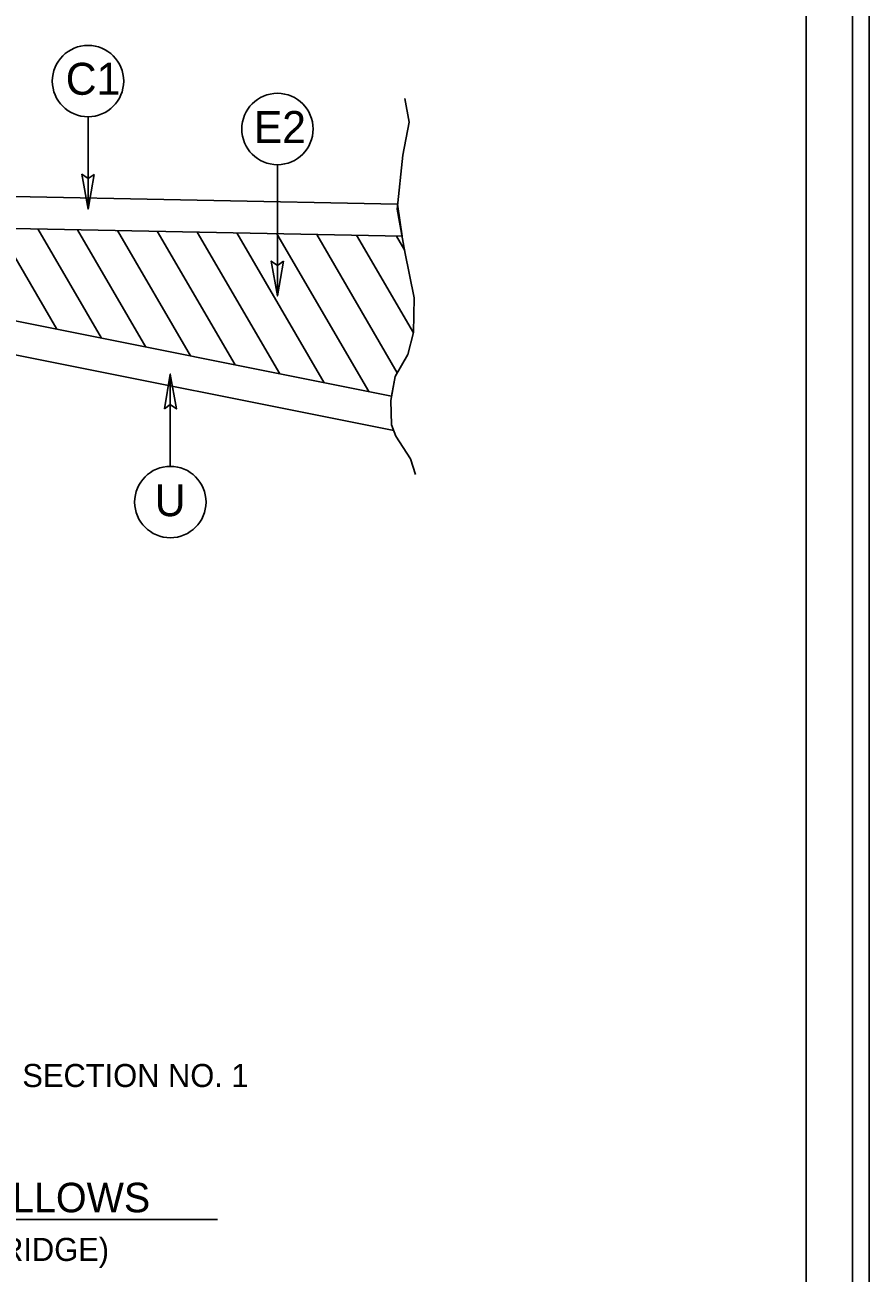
# Model space of a CAD drawing. Extents: x 55823 to 57507, y 47399 to 48499.
# Drawn here: x 57278.5 to 57507.2, y 47946.4 to 48284.4 of the extents above; entities that cross this region are included whole.
import ezdxf

# ---------------------------------------------------------------- set-up
doc = ezdxf.new("R2010")
doc.units = 0
for name, color, linetype in [('Old_Level_1', 7, 'Continuous'), ('Sheet Plot Border Inside CELL', 7, 'Continuous'), ('Sheet Plot Border Outside CELL', 7, 'Continuous'), ('Sheet Typical CELL', 7, 'Continuous'), ('Typical Detail Wedge2 CELL', 7, 'Continuous'), ('Typical ID Circle CELL', 7, 'Continuous'), ('Typical Terminator CELL', 7, 'Continuous'), ('Typical Text ID Circle CELL', 7, 'Continuous')]:
    doc.layers.add(name, color=color, linetype=linetype)

msp = doc.modelspace()

# ---------------------------------------------------------------- linework, layer by layer
at = {"layer": 'Old_Level_1'}
msp.add_line((57090.02, 47960.92), (57330.68, 47960.92), dxfattribs=at)
at = {"layer": 'Sheet Plot Border Inside CELL'}
msp.add_lwpolyline([(57502.66, 48476.93), (55836.16, 48476.93), (55836.16, 47421.83), (57502.66, 47421.83)], close=True, dxfattribs=at)
at = {"layer": 'Sheet Plot Border Outside CELL'}
msp.add_lwpolyline([(57507.16, 48499.38), (55823.16, 48499.38), (55823.16, 47399.38), (57507.16, 47399.38)], close=True, dxfattribs=at)
at = {"layer": 'Sheet Typical CELL'}
msp.add_lwpolyline([(57490.16, 48474.38), (55990.16, 48474.38), (55990.16, 47424.38), (57490.16, 47424.38)], close=True, dxfattribs=at)
at = {"layer": 'Typical Detail Wedge2 CELL'}
for p, q in [((57162.97, 48240.21), (57379.43, 48235.89)), ((57162.99, 48240.21), (57379.43, 48235.89)), ((57379.43, 48235.89), (57380.67, 48227.19)), ((57182.12, 48231.16), (57380.67, 48227.19)), ((57380.67, 48227.19), (57182.12, 48231.16)), ((57162.65, 48226.91), (57377.8, 48183.87)), ((57271.13, 48229.38), (57287.09, 48202.01)), ((57281.93, 48229.17), (57299.18, 48199.6)), ((57292.73, 48228.95), (57311.26, 48197.18)), ((57303.53, 48228.74), (57323.34, 48194.76)), ((57314.32, 48228.52), (57335.42, 48192.35)), ((57325.12, 48228.3), (57347.5, 48189.93)), ((57335.92, 48228.09), (57359.58, 48187.51)), ((57346.72, 48227.87), (57371.66, 48185.1)), ((57357.51, 48227.66), (57379.34, 48190.23)), ((57368.31, 48227.44), (57383.74, 48200.99)), ((57379.11, 48227.23), (57381.36, 48223.36)), ((57163.06, 48217.65), (57378.37, 48174.57))]:
    msp.add_line(p, q, dxfattribs=at)
for points in [[(57381.43, 48264.46), (57382.58, 48258.12), (57380.86, 48249.1), (57379.32, 48234.51), (57381.43, 48222.98), (57383.93, 48210.51), (57383.74, 48201.09), (57382.19, 48195.15), (57378.74, 48189.19), (57377.6, 48182.67), (57377.78, 48176.14), (57378.93, 48173.06), (57382.96, 48166.92), (57384.3, 48162.69)], [(57377.8, 48183.87), (57378.74, 48189.19), (57382.19, 48195.15), (57383.74, 48201.09), (57383.93, 48210.51), (57382.77, 48216.29)]]:
    msp.add_lwpolyline(points, dxfattribs=at)
at = {"layer": 'Typical ID Circle CELL'}
for p, q in [((57295.56, 48259.54), (57295.56, 48234.56)), ((57346.88, 48246.57), (57346.88, 48211.04)), ((57317.86, 48164.87), (57317.86, 48189.86))]:
    msp.add_line(p, q, dxfattribs=at)
for centre in [(57295.56, 48269.21), (57346.88, 48256.23), (57317.86, 48155.2)]:
    msp.add_circle(centre, 9.67, dxfattribs=at)
at = {"layer": 'Typical Terminator CELL'}
for points in [[(57297.18, 48243.93), (57295.56, 48234.56), (57293.89, 48243.98), (57295.56, 48242.78)], [(57297.18, 48243.93), (57295.56, 48234.56), (57293.89, 48243.98), (57295.56, 48242.78)], [(57348.5, 48220.41), (57346.88, 48211.04), (57345.21, 48220.47), (57346.88, 48219.27)], [(57316.25, 48180.48), (57317.86, 48189.86), (57319.53, 48180.43), (57317.86, 48181.63)], [(57316.25, 48180.48), (57317.86, 48189.86), (57319.53, 48180.43), (57317.86, 48181.63)]]:
    msp.add_lwpolyline(points, close=True, dxfattribs=at)

# ---------------------------------------------------------------- texts
at = {"layer": 'Old_Level_1'}
for s, height, p in [('NOTE: TRANSITION FROM EXISTING TO TYPICAL SECTION NO. 1', 6.25, (57077.63, 47996.77)), ('USE TYPICAL SECTION NO. 1 AS FOLLOWS', 8, (57088.9, 47962.85)), ('-L- STA 14+00.00 TO STA 15+46.81 (BEGIN BRIDGE)', 6.25, (57096.87, 47949.67))]:
    msp.add_text(s, height=height, dxfattribs=at).set_placement(p)
at = {"layer": 'Typical Text ID Circle CELL'}
for s, height, p in [('C1', 8.653, (57289.52, 48265.5)), ('E2', 8.653, (57340.45, 48252.44)), ('U', 8.65, (57313.64, 48151.38))]:
    msp.add_text(s, height=height, dxfattribs=at).set_placement(p)

doc.saveas('drawing.dxf')
